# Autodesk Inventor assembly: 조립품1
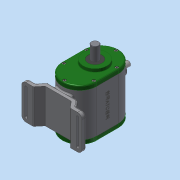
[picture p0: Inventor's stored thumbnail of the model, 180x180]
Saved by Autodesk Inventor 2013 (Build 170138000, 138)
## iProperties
Created: 2018-07
Part Number: 조립품1
Document SubType Name: Assembly
Designer: dgall
Mass: 2430.12 g
Surface Area: 2005.89 cm^2
Volume: 679.263 cm^3
Density: 3.57758 g/cm^3
Author: dgall
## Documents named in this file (14)
- C:\Users\dgall\Desktop\380707V1002\조립품1.iam
- C:\Users\dgall\Desktop\380707V1002\본체.ipt
- C:\Users\dgall\Desktop\380707V1002\가변부품.ipt
- C:\Users\dgall\Desktop\380707V1002\부시.ipt
- C:\Users\dgall\Desktop\380707V1002\슬라이더.ipt
- C:\Users\dgall\Desktop\380707V1002\뒤커버.ipt
- C:\Users\dgall\Desktop\380707V1002\베어링 608.ipt
- C:\Users\dgall\Desktop\380707V1002\볼트 M4.ipt
- C:\Users\dgall\Desktop\380707V1002\오일 실 8 22 7.ipt
- C:\Users\dgall\Desktop\380707V1002\메인축.ipt
- C:\Users\dgall\Desktop\380707V1002\베어링 6003.ipt
- C:\Users\dgall\Desktop\380707V1002\서브축.ipt
- C:\Users\dgall\Desktop\380707V1002\앞커버.ipt
- C:\Users\dgall\Desktop\380707V1002\오일 실 17 32 8.ipt
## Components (1 placed, 1 different names)
1. 가변부품:1
